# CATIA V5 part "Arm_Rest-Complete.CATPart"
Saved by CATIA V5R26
Part number: Arm_Rest
Bounding box of the stored display mesh (mm): x 765.888 to 1405.688, y -781.99 to -669.648, z 394.789 to 524.01
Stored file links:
  D:\LinkedIn Learning\NURBS\CATIA\Arm_Rest-Complete.CATPart
  D:\LinkedIn Learning\NURBS\Arm_Rest.CATPart
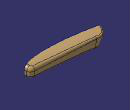
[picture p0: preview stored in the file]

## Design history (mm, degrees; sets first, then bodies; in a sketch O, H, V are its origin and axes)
AxisSystem1: origin (0, 0, 0), X (1, 0, 0), Y (0, 1, 0), Z (0, 0, 1)
Set1 "REF DATA"
  CLDGeom1 "TOP"
  CLDGeom2 "FRONT"
  CLDGeom3 "AFT_BLEND"
  CLDGeom4 "END_AFT"
  CLDGeom5 "FORWARD_BLEND"
  CLDGeom6 "BOTTOM"
  CLDGeom7 "END_FORWARD"
  CLDGeom8 "UPPER_BLENDS"
  CLDGeom9 "LOWER_BLENDS"
  DatumSurface1 "DOOR_TRIM_SURFACE"
Set2 "FORM"
  Set3 "SLABS"
    DatumSurface2 to DatumSurface6
  Set4 "CURVES"
    St3DCurveFeature1 "CATSt3DCurveFeatureName": Order 6, CreationType 1, ClosureMode false, ConstructionPoints ({point type Coord, X 877.7977, Y 0, Z 551.1449}; {point type Coord, X 861.9594, Y 0, Z 330.43}), SymmetryMode false
    St3DCurveFeature2 "CATSt3DCurveFeatureName": Order 6, CreationType 1, ClosureMode false, ConstructionPoints ({point type Coord, X 1369.3867, Y 0, Z 551.9965}; {point type Coord, X 1358.4038, Y 0, Z 335.6826}), SymmetryMode false
    Intersect1: ToIntersect1 DatumSurface4, ToIntersect2 DatumSurface5
    Intersect2: ToIntersect1 DatumSurface6, ToIntersect2 DatumSurface4
    CurvePar1: Offset Intersect2, Support DatumSurface6, Offset2 0, Offset1 30
    CurvePar2: Offset Intersect1, Support DatumSurface5, Offset2 50, Offset1 20
    Project1: ToProject St3DCurveFeature1, Support DatumSurface4, Direction edge [YZ plane of AxisSystem1 | XY plane of AxisSystem1]
    Project2: ToProject St3DCurveFeature2, Support DatumSurface4, Direction edge [YZ plane of AxisSystem1 | XY plane of AxisSystem1]
    Project3: ToProject St3DCurveFeature2, Support StTopoTypeFeature3, Direction edge [YZ plane of AxisSystem1 | XY plane of AxisSystem1]
    Project4: ToProject St3DCurveFeature1, Support StTopoTypeFeature3, Direction edge [YZ plane of AxisSystem1 | XY plane of AxisSystem1]
    Intersect3: ToIntersect1 edge of StTopoTypeFeature1, ToIntersect2 CurvePar2
    Intersect4: ToIntersect1 edge of StTopoTypeFeature2, ToIntersect2 CurvePar1
    Project5: ToProject Intersect4, Support edge of StTopoTypeFeature2
    Project6: ToProject Intersect3, Support edge of StTopoTypeFeature1
    Line1: type PtPt, FirstPoint Intersect3, SecondPoint Project6, Support StTopoTypeFeature1
    Line2: type PtPt, FirstPoint Intersect4, SecondPoint Project5, Support StTopoTypeFeature2
    Curve1: Elements (Intersect4; vertex of Project3), Support Blend2
    Curve2: Elements (Project5; vertex of Project3), Support DatumSurface2
    Curve3: Elements (vertex of Project4; Intersect3), Support Blend1
    Curve4: Elements (vertex of Project4; Project6), Support DatumSurface2
  Set5 "BLENDS"
    Blend1: StartLimit {blendlimit Curve Project1, Support DatumSurface4, TensionValues 1.1}, EndLimit {blendlimit Curve CurvePar2, Support DatumSurface5, TensionValues 1}
    Blend2: StartLimit {blendlimit Curve CurvePar1, Support DatumSurface6, TensionValues 0.9}, EndLimit {blendlimit Curve Project2, Support DatumSurface4, TensionValues 0.8}
    StTopoTypeFeature1 "CATStTopoTypeFeatureName": Children 10
    StTopoTypeFeature2 "CATStTopoTypeFeatureName": Children 40
    StTopoTypeFeature3 "CATStTopoTypeFeatureName": nls://CATStFeaturesStartUpsNLS/TopoVarRadiCke 35, nls://CATStFeaturesStartUpsNLS/TopoVarRadiCke 15
    Loft1: Sections (Line2; Project3), StartSectionTangent StTopoTypeFeature2, EndSectionTangent StTopoTypeFeature3, Guides ({loftguide GuideCurve Curve1, GuideTangent Blend2}; {loftguide GuideCurve Curve2, GuideTangent DatumSurface2})
    Loft2: Sections (Project4; Line1), StartSectionTangent StTopoTypeFeature3, EndSectionTangent StTopoTypeFeature1, Guides ({loftguide GuideCurve Curve3, GuideTangent Blend1}; {loftguide GuideCurve Curve4, GuideTangent DatumSurface2})
  Set6 "SPLITS"
    Split1: ToCut DatumSurface4, Cutting (Project1; edge of StTopoTypeFeature3; Project2)
    Split2: ToCut Blend2, Cutting Curve1
    Split3: ToCut DatumSurface6, Cutting (CurvePar1; edge of StTopoTypeFeature2)
    Split4: ToCut Blend1, Cutting Curve3
    Split5: ToCut DatumSurface5, Cutting (CurvePar2; edge of StTopoTypeFeature1)
    Split6: ToCut StTopoTypeFeature1, Cutting Line1
    Split7: ToCut StTopoTypeFeature3, Cutting (Project4; Project3)
    Split8: ToCut StTopoTypeFeature2, Cutting Line2
    Split9: ToCut DatumSurface2, Cutting (edge of StTopoTypeFeature3; edge of StTopoTypeFeature2; Curve2; edge of StTopoTypeFeature1; Curve4)
  Join1: Elements (Split9; Loft1; Loft2; Split6; Split7; Split8; Split2; Split4; Split5; Split1; Split3)
  StTopoTypeFeature4 "CATStTopoTypeFeatureName": Children 13
  Split10: ToCut StTopoTypeFeature4, Cutting DatumSurface1
Body1 (main body)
